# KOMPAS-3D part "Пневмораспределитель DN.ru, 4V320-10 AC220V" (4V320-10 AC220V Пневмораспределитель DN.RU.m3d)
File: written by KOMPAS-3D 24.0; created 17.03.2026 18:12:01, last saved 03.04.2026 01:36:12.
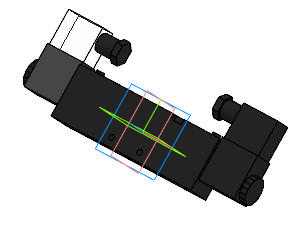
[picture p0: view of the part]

Document properties: Автор: R2D2; Полное имя файла: E:\Работа\Зайцев\Аксессуары для пневмоприводов\Пневмораспределители DN.ru\4V320 AC220V Пневмораспределитель DN.RU\4V320-10 AC220V Пневмораспределитель DN.RU\исходные материалы\4V320-10 AC220V Пневмораспределитель DN.RU.m3d

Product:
- Body: Тело 1  | qty 1
    Масса: 1.552409
- Body: Тело 3  | qty 1
    Масса: 1.552409
- Part/product: Пневмораспределитель DN.ru  | designation 4V320-10 AC220V
    Масса: 1.2
    Раздел спецификации: Прочие изделия
    Примечание: D290-00335

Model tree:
1. Эскиз:1
2. Элемент выдавливания:1
     Расстояние 1 = 118.8
3. Эскиз:2  (with: Грань.Элемент выдавливания:1)
4. Элемент выдавливания:2
     Расстояние 2 = 1.4
5. Эскиз:3  (with: Грань.Элемент выдавливания:1, Ребро.Элемент выдавливания:1)
6. Элемент выдавливания:3
     Расстояние 2 = 27
7. Эскиз:4  (with: Грань.Элемент выдавливания:1, Ребро.Элемент выдавливания:1)
8. Элемент выдавливания:4
     Расстояние 1 = 30
9. Эскиз:5  (with: Грань.Элемент выдавливания:4, Ребро.Элемент выдавливания:4)
10. Элемент выдавливания:5
     Расстояние 1 = 27
11. Эскиз:6  (with: Грань.Элемент выдавливания:4)
12. Элемент выдавливания:6
     Расстояние 1 = 5
13. Эскиз:7  (with: Грань.Элемент выдавливания:5)
14. Элемент выдавливания:7
     Расстояние 1 = 14
15. Эскиз:8  (with: Грань.Элемент выдавливания:7, Ребро.Элемент выдавливания:7)
16. Элемент выдавливания:8
     Расстояние 1 = 5
17. Эскиз:9  (with: Грань.Элемент выдавливания:1, Ребро.Элемент выдавливания:4)
18. Элемент выдавливания:9
     Расстояние 1 = 2.4
19. Эскиз:12  (with: Грань.Элемент выдавливания:9, Ребро.Элемент выдавливания:9)
20. Элемент выдавливания:12
     Расстояние 2 = 1
21. Эскиз:10  (with: Грань.Элемент выдавливания:1)
22. Элемент выдавливания:10
     Расстояние 2 = 12
23. пазы  (with: Грань.Элемент выдавливания:1, Ребро.Элемент выдавливания:3)
24. Элемент выдавливания:11
     Расстояние 2 = 5
25. Зеркальный массив:2
26. Экземпляр ( 1 )
27. Экземпляр ( 2 )  (with: Элемент выдавливания:4, Элемент выдавливания:6, Элемент выдавливания:5, Элемент выдавливания:7, Элемент выдавливания:8, Элемент выдавливания:9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)
28. Эскиз:13  (with: Грань.Элемент выдавливания:1)
29. Элемент выдавливания:13
     Расстояние 2 = 12
30. Эскиз:14  (with: Грань.Элемент выдавливания:1)  (labels: Вершина.Элемент выдавливания:6.Экземпляр ( 2 ))
31. Элемент выдавливания:14
     Расстояние 2 = 40
32. Эскиз:15  (with: Грань.Элемент выдавливания:1, Ребро.Элемент выдавливания:14)
33. Элемент выдавливания:15
     Расстояние 2 = 4

Expressions: 4V320-10 AC220V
